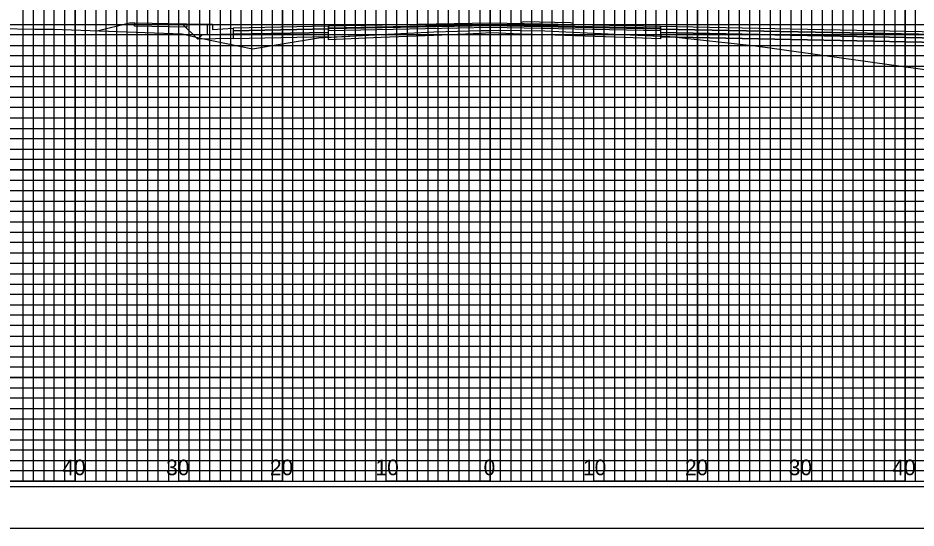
# Model space of a CAD drawing. Extents: x -13 to 760, y -5 to 1491.
# Drawn here: x 551.2 to 637.8, y -4.5 to 44.6 of the extents above; entities that cross this region are included whole.
import ezdxf

# ---------------------------------------------------------------- set-up
doc = ezdxf.new("R2010")
doc.units = 0
for name, color, linetype in [('Exist XS Ground Line', 7, 'Continuous'), ('Prop CMT Pvmt Course 1', 7, 'Continuous'), ('Prop CMT Pvmt Course 2', 7, 'Continuous'), ('Prop CMT Pvmt Course 3', 7, 'Continuous'), ('Prop CMT Subgrade Earthwork', 7, 'Continuous'), ('Prop Conc 4in Sidewalk', 7, 'Continuous'), ('Prop Conc Curb and Gutter', 7, 'Continuous'), ('Prop Conc Island Cover', 7, 'Continuous'), ('Prop Corridor Mesh Bottom', 7, 'Continuous'), ('Prop XS Alignment Label', 7, 'Continuous'), ('Prop XS Finish Grade', 7, 'Continuous'), ('Prop XS Offset Labels', 7, 'Continuous'), ('Scratch_Level_9', 7, 'Continuous'), ('Sheet Cross Section CELL', 7, 'Continuous'), ('Sheet Cross Section Grid Major CELL', 7, 'Continuous'), ('Sheet Cross Section Grid Middle CELL', 7, 'Continuous'), ('Sheet Cross Section Grid Minor 1 CELL', 7, 'Continuous'), ('Sheet Cross Section Grid Minor 2 CELL', 7, 'Continuous'), ('Sheet Cutting Line CELL', 7, 'Continuous'), ('Sheet DOT Grid CELL', 7, 'Continuous'), ('Sheet Plot Border Inside CELL', 7, 'Continuous'), ('Sheet Plot Border Outside CELL', 7, 'Continuous')]:
    doc.layers.add(name, color=color, linetype=linetype)

msp = doc.modelspace()

# ---------------------------------------------------------------- linework, layer by layer
at = {"layer": 'Exist XS Ground Line'}
msp.add_lwpolyline([(542.685, 43.759), (552.838, 43.563), (554.589, 43.56), (567.017, 43.103), (568.791, 42.682), (573.796, 41.659), (576.673, 42.133), (580.165, 42.733), (586.204, 43.049), (591.275, 43.287), (595.851, 43.419), (597.528, 43.464), (599.615, 43.427), (601.967, 43.392), (608.746, 43.087), (614.019, 42.844), (622.273, 41.96), (644.822, 38.821), (671.472, 36.064), (671.52, 36.065), (671.642, 36.063), (671.67, 36.062), (672.336, 36.011), (697.393, 34.425)], dxfattribs=at)
msp.add_lwpolyline([(542.685, 43.759), (552.838, 43.563), (554.589, 43.56), (567.017, 43.103), (568.791, 42.682), (573.796, 41.659), (576.673, 42.133), (580.165, 42.733), (586.204, 43.049), (591.275, 43.287), (595.851, 43.419), (597.528, 43.464), (599.615, 43.427), (601.967, 43.392), (608.746, 43.087), (614.019, 42.844), (622.273, 41.96), (644.822, 38.821), (671.472, 36.064), (671.52, 36.065), (671.642, 36.063), (671.67, 36.062), (672.336, 36.011), (697.393, 34.425)], dxfattribs=at)
at = {"layer": 'Prop CMT Pvmt Course 1'}
for points in [[(581.134, 43.838), (581.134, 43.671), (596.7, 43.982), (596.7, 43.982), (596.7, 43.982), (613.132, 43.654), (613.132, 43.82), (613.132, 43.82), (596.7, 44.149), (596.7, 44.149), (596.7, 44.149), (581.134, 43.838), (581.134, 43.838)], [(581.134, 43.838), (571.952, 43.654), (571.952, 43.654), (571.952, 43.404), (581.134, 43.588), (581.134, 43.588), (581.134, 43.838), (581.134, 43.838), (581.134, 43.838)], [(613.132, 43.82), (613.132, 43.82), (613.132, 43.82), (613.132, 43.57), (613.132, 43.57), (644.63, 42.94), (644.63, 43.19), (644.63, 43.19), (613.132, 43.82)]]:
    msp.add_lwpolyline(points, dxfattribs=at)
at = {"layer": 'Prop CMT Pvmt Course 2'}
for points in [[(581.134, 43.588), (571.952, 43.404), (571.952, 43.404), (571.952, 43.071), (581.134, 43.254), (581.134, 43.254), (581.134, 43.588), (581.134, 43.588), (581.134, 43.588)], [(581.134, 43.671), (581.134, 43.609), (596.7, 43.92), (596.7, 43.92), (596.7, 43.92), (613.132, 43.591), (613.132, 43.654), (613.132, 43.654), (596.7, 43.982), (596.7, 43.982), (596.7, 43.982), (581.134, 43.671), (581.134, 43.671)], [(613.132, 43.57), (613.132, 43.57), (613.132, 43.57), (613.132, 43.237), (613.132, 43.237), (644.63, 42.607), (644.63, 42.94), (644.63, 42.94), (613.132, 43.57)]]:
    msp.add_lwpolyline(points, dxfattribs=at)
at = {"layer": 'Prop CMT Pvmt Course 3'}
for points in [[(581.134, 43.609), (581.134, 43.442), (596.7, 43.753), (596.7, 43.753), (596.7, 43.753), (613.132, 43.425), (613.132, 43.591), (613.132, 43.591), (596.7, 43.92), (596.7, 43.92), (596.7, 43.92), (581.134, 43.609), (581.134, 43.609)], [(571.952, 43.071), (571.952, 42.654), (568.526, 42.586), (568.951, 43.011), (571.952, 43.071)], [(581.134, 43.254), (571.952, 43.071), (571.952, 43.071), (571.952, 42.654), (581.134, 42.838), (581.134, 42.838), (581.134, 43.254), (581.134, 43.254), (581.134, 43.254)], [(613.132, 43.237), (613.132, 43.237), (613.132, 43.237), (613.132, 42.82), (613.132, 42.82), (644.63, 42.19), (644.63, 42.607), (644.63, 42.607), (613.132, 43.237)]]:
    msp.add_lwpolyline(points, dxfattribs=at)
at = {"layer": 'Prop CMT Subgrade Earthwork'}
for points in [[(568.526, 42.586), (567.029, 44.083)], [(571.952, 42.654), (568.526, 42.586)], [(571.952, 42.654), (581.134, 42.838), (581.134, 42.838)], [(644.63, 42.19), (613.132, 42.82), (613.132, 42.82)]]:
    msp.add_lwpolyline(points, dxfattribs=at)
at = {"layer": 'Prop Conc 4in Sidewalk'}
msp.add_lwpolyline([(567.451, 44.074), (567.461, 43.741), (562.441, 43.841), (562.451, 44.174), (567.451, 44.074)], dxfattribs=at)
at = {"layer": 'Prop Conc Curb and Gutter'}
msp.add_lwpolyline([(571.952, 43.654), (571.952, 43.654), (571.952, 43.654), (571.952, 43.071), (571.952, 43.071), (569.451, 43.021), (569.451, 44.034), (569.451, 44.034), (569.951, 44.034), (569.951, 44.034), (569.951, 44.034), (569.952, 43.534), (571.952, 43.654)], dxfattribs=at)
at = {"layer": 'Prop Conc Island Cover'}
msp.add_lwpolyline([(599.7, 44.214), (599.7, 44.089), (599.7, 44.089), (604.7, 43.989), (604.7, 44.114), (604.7, 44.114), (604.45, 44.177), (604.45, 44.177), (599.953, 44.277), (599.953, 44.277), (599.953, 44.277), (599.7, 44.214), (599.7, 44.214)], dxfattribs=at)
at = {"layer": 'Prop Corridor Mesh Bottom'}
for points in [[(595.851, 43.419), (596.7, 43.442), (596.7, 43.442), (596.7, 43.192), (595.851, 43.156), (595.851, 43.156), (591.275, 42.962), (591.275, 42.962), (586.204, 42.748), (586.204, 42.748), (581.134, 42.533), (581.134, 42.533), (581.134, 42.783), (581.134, 42.783), (581.134, 42.783), (586.204, 43.049), (586.204, 43.049), (591.275, 43.287), (591.275, 43.287), (595.851, 43.419), (595.851, 43.419)], [(608.746, 43.087), (613.132, 42.885), (613.132, 42.885), (613.132, 42.634), (608.746, 42.783), (608.746, 42.783), (601.967, 43.013), (601.967, 43.013), (601.967, 43.013), (599.615, 43.093), (599.615, 43.093), (597.528, 43.164), (596.7, 43.192), (596.7, 43.192), (596.7, 43.442), (596.7, 43.442), (596.7, 43.442), (597.528, 43.464), (599.615, 43.427), (599.615, 43.427), (601.967, 43.392), (601.967, 43.392), (601.967, 43.392), (608.746, 43.087), (608.746, 43.087)]]:
    msp.add_lwpolyline(points, dxfattribs=at)
at = {"layer": 'Prop XS Finish Grade'}
for points in [[(558.831, 43.404), (561.951, 44.184), (561.951, 44.184)], [(561.951, 44.184), (562.451, 44.174), (562.451, 44.174)], [(567.451, 44.074), (569.451, 44.034), (569.451, 44.034)]]:
    msp.add_lwpolyline(points, dxfattribs=at)
at = {"layer": 'Scratch_Level_9'}
msp.add_lwpolyline([(571.952, 43.654), (571.952, 43.404)], dxfattribs=at)
at = {"layer": 'Sheet Cross Section CELL'}
msp.add_lwpolyline([(756.7, 210), (436.7, 210), (436.7, 0), (756.7, 0)], close=True, dxfattribs=at)
at = {"layer": 'Sheet Cross Section Grid Major CELL'}
for p, q in [((556.7, 210), (556.7, 0)), ((566.7, 0), (566.7, 210)), ((576.7, 210), (576.7, 0)), ((586.7, 0), (586.7, 210)), ((596.7, 210), (596.7, 0)), ((606.7, 0), (606.7, 210)), ((616.7, 210), (616.7, 0)), ((626.7, 0), (626.7, 210)), ((636.7, 210), (636.7, 0)), ((556.7, 0), (546.7, 0)), ((576.7, 0), (566.7, 0)), ((596.7, 0), (586.7, 0)), ((616.7, 0), (606.7, 0)), ((636.7, 0), (626.7, 0))]:
    msp.add_line(p, q, dxfattribs=at)
for points in [[(436.7, 40), (756.7, 40), (756.7, 30), (436.7, 30)], [(436.7, 20), (756.7, 20), (756.7, 10), (436.7, 10)]]:
    msp.add_lwpolyline(points, dxfattribs=at)
at = {"layer": 'Sheet Cross Section Grid Middle CELL'}
for points in [[(541.7, 0), (551.7, 0), (551.7, 210)], [(561.7, 210), (561.7, 0), (571.7, 0), (571.7, 210)], [(581.7, 210), (581.7, 0), (591.7, 0), (591.7, 210)], [(601.7, 210), (601.7, 0), (611.7, 0), (611.7, 210)], [(621.7, 210), (621.7, 0), (631.7, 0), (631.7, 210)], [(436.7, 25), (756.7, 25), (756.7, 35), (436.7, 35)], [(436.7, 5), (756.7, 5), (756.7, 15), (436.7, 15)]]:
    msp.add_lwpolyline(points, dxfattribs=at)
at = {"layer": 'Sheet Cross Section Grid Minor 1 CELL'}
for points in [[(436.7, 44), (756.7, 44), (756.7, 43), (436.7, 43)], [(436.7, 42), (756.7, 42), (756.7, 41), (436.7, 41)], [(436.7, 39), (756.7, 39), (756.7, 38), (436.7, 38)], [(436.7, 37), (756.7, 37), (756.7, 36), (436.7, 36)], [(436.7, 34), (756.7, 34), (756.7, 33), (436.7, 33)], [(436.7, 32), (756.7, 32), (756.7, 31), (436.7, 31)], [(436.7, 29), (756.7, 29), (756.7, 28), (436.7, 28)], [(436.7, 27), (756.7, 27), (756.7, 26), (436.7, 26)], [(436.7, 24), (756.7, 24), (756.7, 23), (436.7, 23)], [(436.7, 22), (756.7, 22), (756.7, 21), (436.7, 21)], [(436.7, 19), (756.7, 19), (756.7, 18), (436.7, 18)], [(436.7, 17), (756.7, 17), (756.7, 16), (436.7, 16)], [(436.7, 14), (756.7, 14), (756.7, 13), (436.7, 13)], [(436.7, 12), (756.7, 12), (756.7, 11), (436.7, 11)], [(436.7, 9), (756.7, 9), (756.7, 8), (436.7, 8)], [(436.7, 7), (756.7, 7), (756.7, 6), (436.7, 6)], [(436.7, 4), (756.7, 4), (756.7, 3), (436.7, 3)], [(436.7, 2), (756.7, 2), (756.7, 1), (436.7, 1)]]:
    msp.add_lwpolyline(points, dxfattribs=at)
at = {"layer": 'Sheet Cross Section Grid Minor 2 CELL'}
for points in [[(551.7, 0), (552.7, 0), (552.7, 210), (553.7, 210), (553.7, 0)], [(553.7, 0), (554.7, 0), (554.7, 210), (555.7, 210), (555.7, 0)], [(556.7, 0), (557.7, 0), (557.7, 210), (558.7, 210), (558.7, 0)], [(558.7, 0), (559.7, 0), (559.7, 210), (560.7, 210), (560.7, 0)], [(561.7, 0), (562.7, 0), (562.7, 210), (563.7, 210), (563.7, 0)], [(563.7, 0), (564.7, 0), (564.7, 210), (565.7, 210), (565.7, 0)], [(566.7, 0), (567.7, 0), (567.7, 210), (568.7, 210), (568.7, 0)], [(568.7, 0), (569.7, 0), (569.7, 210), (570.7, 210), (570.7, 0)], [(571.7, 0), (572.7, 0), (572.7, 210), (573.7, 210), (573.7, 0)], [(573.7, 0), (574.7, 0), (574.7, 210), (575.7, 210), (575.7, 0)], [(576.7, 0), (577.7, 0), (577.7, 210), (578.7, 210), (578.7, 0)], [(578.7, 0), (579.7, 0), (579.7, 210), (580.7, 210), (580.7, 0)], [(581.7, 0), (582.7, 0), (582.7, 210), (583.7, 210), (583.7, 0)], [(583.7, 0), (584.7, 0), (584.7, 210), (585.7, 210), (585.7, 0)], [(586.7, 0), (587.7, 0), (587.7, 210), (588.7, 210), (588.7, 0)], [(588.7, 0), (589.7, 0), (589.7, 210), (590.7, 210), (590.7, 0)], [(591.7, 0), (592.7, 0), (592.7, 210), (593.7, 210), (593.7, 0)], [(593.7, 0), (594.7, 0), (594.7, 210), (595.7, 210), (595.7, 0)], [(596.7, 0), (597.7, 0), (597.7, 210), (598.7, 210), (598.7, 0)], [(598.7, 0), (599.7, 0), (599.7, 210), (600.7, 210), (600.7, 0)], [(601.7, 0), (602.7, 0), (602.7, 210), (603.7, 210), (603.7, 0)], [(603.7, 0), (604.7, 0), (604.7, 210), (605.7, 210), (605.7, 0)], [(606.7, 0), (607.7, 0), (607.7, 210), (608.7, 210), (608.7, 0)], [(608.7, 0), (609.7, 0), (609.7, 210), (610.7, 210), (610.7, 0)], [(611.7, 0), (612.7, 0), (612.7, 210), (613.7, 210), (613.7, 0)], [(613.7, 0), (614.7, 0), (614.7, 210), (615.7, 210), (615.7, 0)], [(616.7, 0), (617.7, 0), (617.7, 210), (618.7, 210), (618.7, 0)], [(618.7, 0), (619.7, 0), (619.7, 210), (620.7, 210), (620.7, 0)], [(621.7, 0), (622.7, 0), (622.7, 210), (623.7, 210), (623.7, 0)], [(623.7, 0), (624.7, 0), (624.7, 210), (625.7, 210), (625.7, 0)], [(626.7, 0), (627.7, 0), (627.7, 210), (628.7, 210), (628.7, 0)], [(628.7, 0), (629.7, 0), (629.7, 210), (630.7, 210), (630.7, 0)], [(631.7, 0), (632.7, 0), (632.7, 210), (633.7, 210), (633.7, 0)], [(633.7, 0), (634.7, 0), (634.7, 210), (635.7, 210), (635.7, 0)], [(636.7, 0), (637.7, 0), (637.7, 210), (638.7, 210), (638.7, 0)]]:
    msp.add_lwpolyline(points, dxfattribs=at)
at = {"layer": 'Sheet Cutting Line CELL'}
msp.add_line((423.3, -4.5), (760, -4.5), dxfattribs=at)
at = {"layer": 'Sheet DOT Grid CELL'}
for p, q in [((556.7, 0), (556.7, 210)), ((566.7, 0), (566.7, 210)), ((576.7, 0), (576.7, 210)), ((586.7, 0), (586.7, 210)), ((596.7, 0), (596.7, 210)), ((606.7, 0), (606.7, 210)), ((616.7, 0), (616.7, 210)), ((626.7, 0), (626.7, 210)), ((636.7, 0), (636.7, 210)), ((436.7, 40), (756.7, 40)), ((436.7, 30), (756.7, 30)), ((436.7, 20), (756.7, 20)), ((436.7, 10), (756.7, 10))]:
    msp.add_line(p, q, dxfattribs=at)
at = {"layer": 'Sheet Plot Border Inside CELL'}
msp.add_lwpolyline([(425.9, -0.5), (759.1, -0.5), (759.1, 210.5), (425.9, 210.5)], close=True, dxfattribs=at)
at = {"layer": 'Sheet Plot Border Outside CELL'}
msp.add_lwpolyline([(423.3, -4.5), (760, -4.5), (760, 214.5), (423.3, 214.5)], close=True, dxfattribs=at)

# ---------------------------------------------------------------- texts
at = {"layer": 'Prop XS Alignment Label'}
msp.add_text('.', height=0.01, dxfattribs=at).set_placement((596.967, 5.327))
at = {"layer": 'Prop XS Offset Labels'}
for s, p in [('40', (555.485, 0.588)), ('30', (565.485, 0.588)), ('20', (575.485, 0.588)), ('10', (585.664, 0.588)), ('0', (596.078, 0.588)), ('0', (596.078, 0.588)), ('10', (605.664, 0.588)), ('20', (615.485, 0.588)), ('30', (625.485, 0.588)), ('40', (635.485, 0.588))]:
    msp.add_text(s, height=1.5, dxfattribs=at).set_placement(p)
at = {"layer": 'Scratch_Level_9'}
for p in [(562.45, 44.173), (596.699, 44.148), (558.83, 43.403), (567.45, 44.073), (569.951, 43.533), (571.951, 43.653), (571.951, 43.653)]:
    msp.add_text('X', height=0.0025, dxfattribs=at).set_placement(p)

doc.saveas('drawing.dxf')
